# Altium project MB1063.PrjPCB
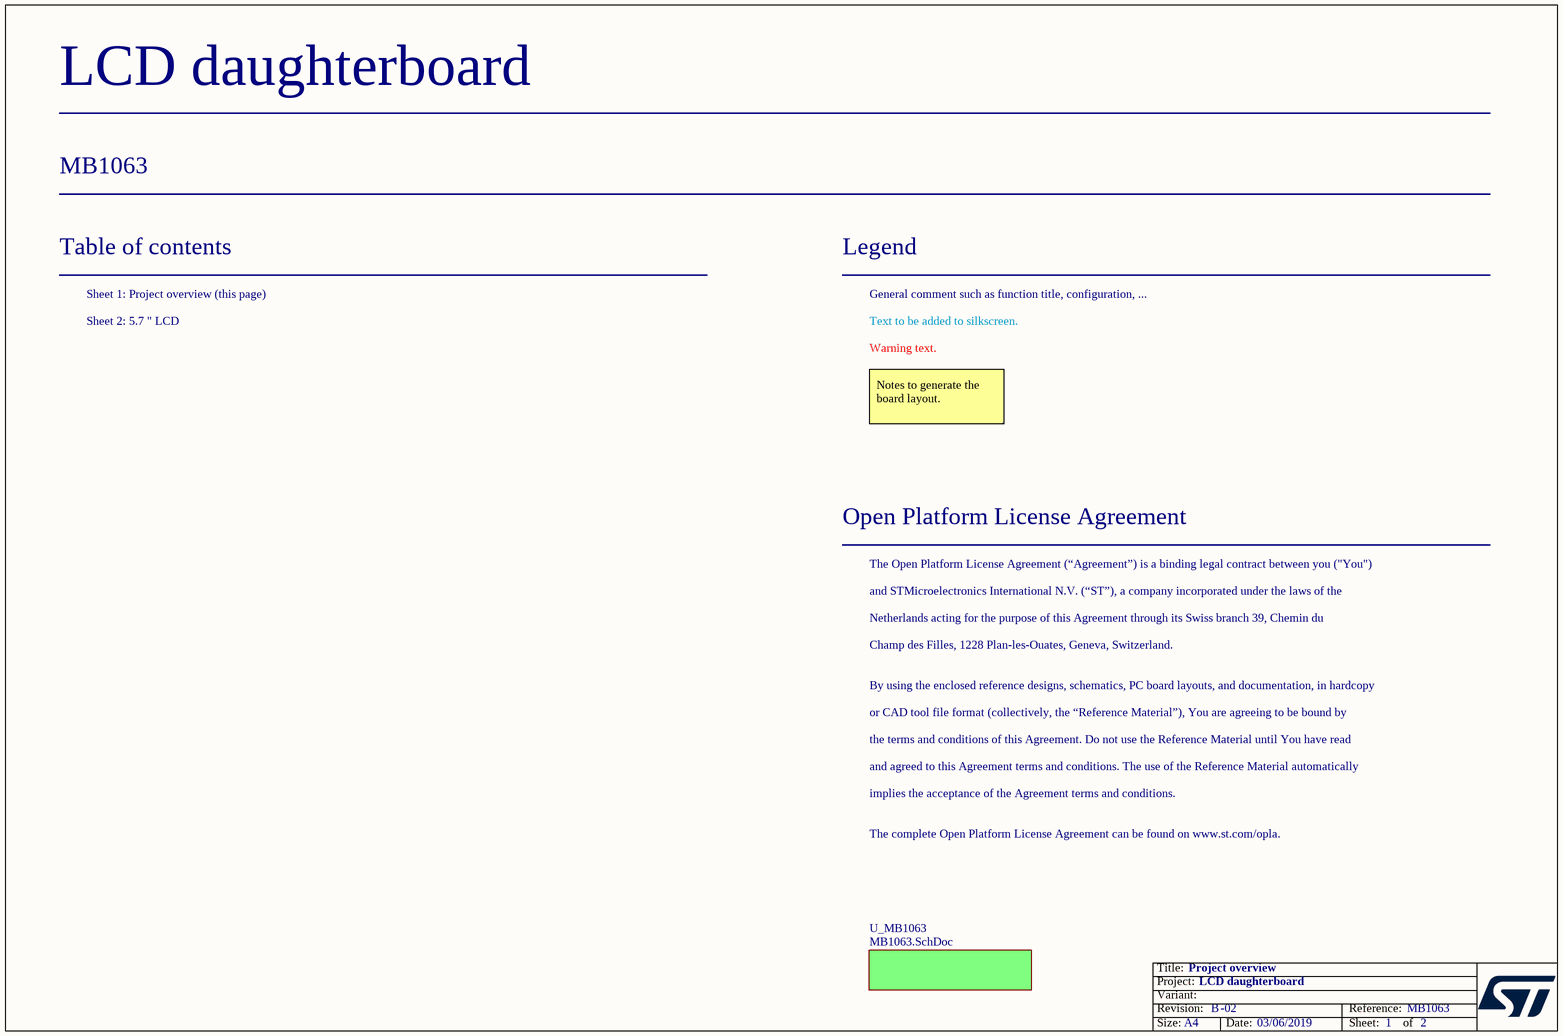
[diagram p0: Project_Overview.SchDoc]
Board_Assembly_Revision: 02; Board_Document_Date: 03/06/2019; Board_Name: LCD daughterboard; Board_PCB_Revision: B; Board_Reference: MB1063
2 sheets, 31 parts. Net scope: global (net labels, ports and power ports of the same name join across sheets).
Sheets:
  Project_Overview.SchDoc
    U_MB1063 = MB1063.SchDoc

## Sheet Project_Overview.SchDoc: Project overview
size A4; Date: Not used; ApprovedBy: Not used; CheckedBy: Not used; Author: Not used; CompanyName: STMicroelectronics; DrawnBy: Not used; Engineer: Not used; Organization: Not used; Address1: Not used; Address2: Not used; Address3: Not used; Address4: Not used; DocumentNumber: 1; Revision: Not used; SheetNumber: 1; SheetTotal: 2

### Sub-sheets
U_MB1063 = MB1063.SchDoc: no entries

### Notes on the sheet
- Table of contents
- Sheet 1: Project overview (this page)
- Legend
- General comment such as function title, configuration, ...
- Sheet 2: 5.7 " LCD
- Text to be added to silkscreen.
- Warning text.
- Notes to generate the board layout.
- Open Platform License Agreement
- The Open Platform License Agreement (“Agreement”) is a binding legal contract between you ("You")
- and STMicroelectronics International N.V. (“ST”), a company incorporated under the laws of the
- Netherlands acting for the purpose of this Agreement through its Swiss branch 39, Chemin du
- Champ des Filles, 1228 Plan-les-Ouates, Geneva, Switzerland.
- By using the enclosed reference designs, schematics, PC board layouts, and documentation, in hardcopy
- or CAD tool file format (collectively, the “Reference Material”), You are agreeing to be bound by
- the terms and conditions of this Agreement. Do not use the Reference Material until You have read
- and agreed to this Agreement terms and conditions. The use of the Reference Material automatically
- implies the acceptance of the Agreement terms and conditions.
- The complete Open Platform License Agreement can be found on www.st.com/opla.

## Sheet MB1063.SchDoc: 5.7 " LCD
size A4; DocumentNumber: 2; Revision: B.2(PCB.SCH); SheetNumber: 2; SheetTotal: 2
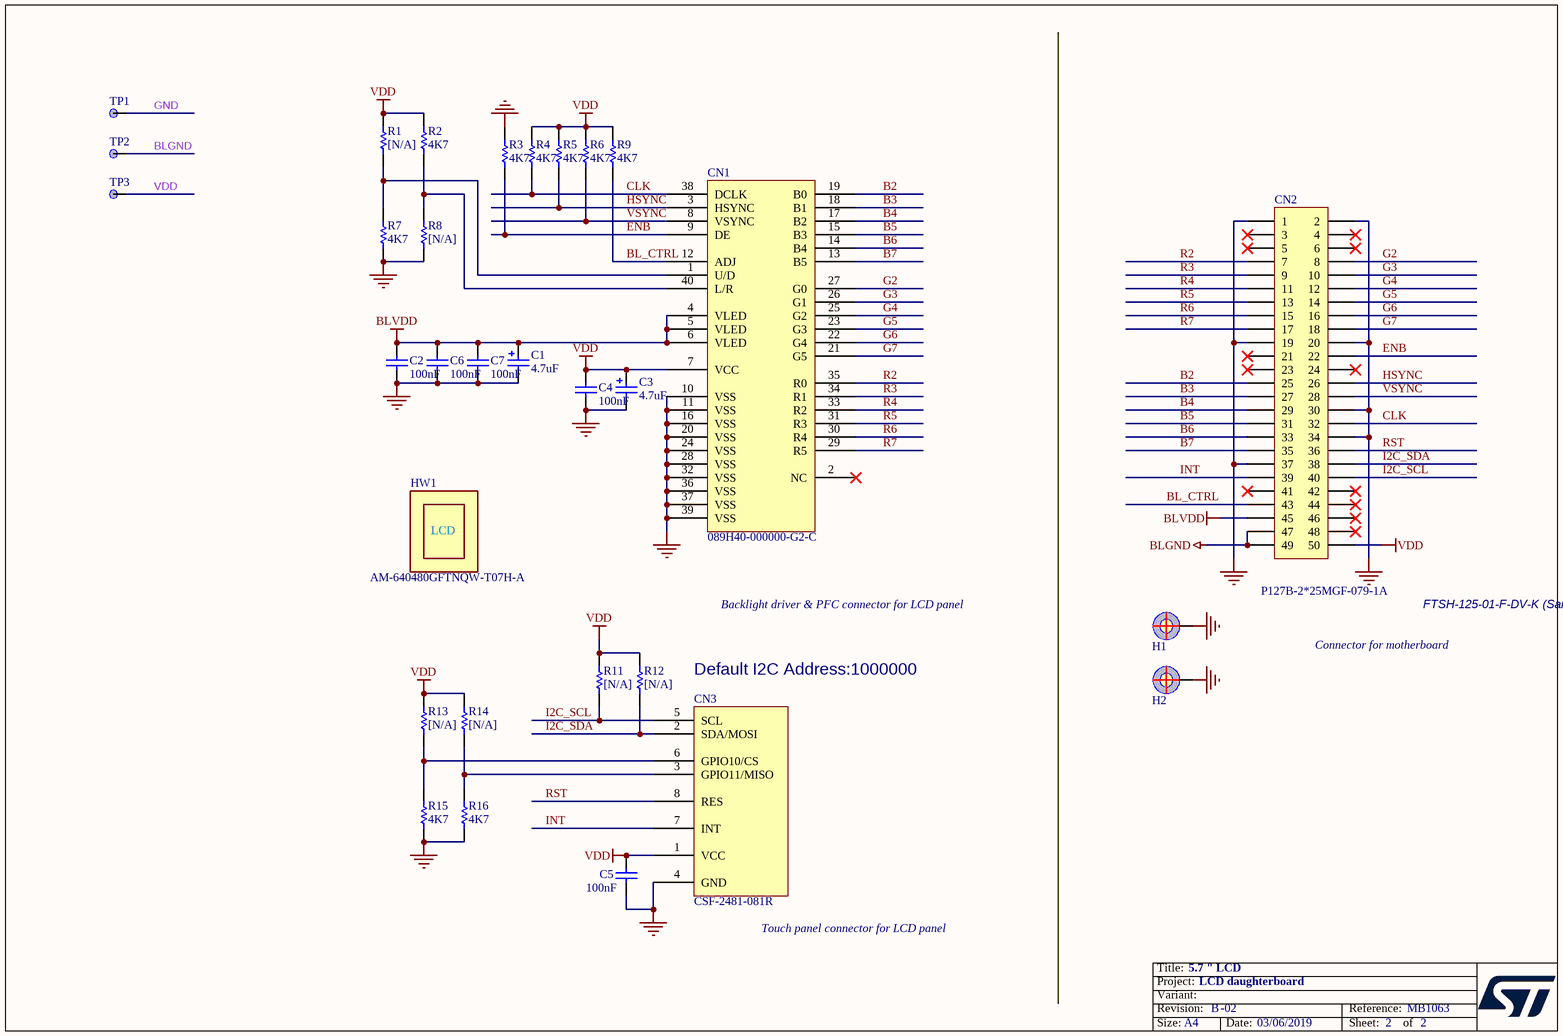
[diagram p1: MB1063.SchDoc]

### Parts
C1  4.7uF  [TAN-A]
C2  100nF  [0603C]
C3  4.7uF  [TAN-A]
C4  100nF  [0603C]
C5  100nF  [0603C]
C6  100nF  [0603C]
C7  100nF  [0603C]
CN1  089H40-000000-G2-C  [FPC40_0R5_089H40LY-FPC_REV]
CN2  P127B-2*25MGF-079-1A  [FTSH-125-01-F-DV]
CN3  CSF-2481-081R  [FPC8_0R5_089H08_LY-FPC_REV]
H1  POSITION HOLE  [HOLE_C9D4R5]  (value not drawn)
H2  POSITION HOLE  [HOLE_C9D4R5]  (value not drawn)
HW1  AM-640480GFTNQW-T07H-A  (mechanical)
R1  [N/A]  [0603R]
R2  4K7  [0603R]
R3  4K7  [0603R]
R4  4K7  [0603R]
R5  4K7  [0603R]
R6  4K7  [0603R]
R7  4K7  [0603R]
R8  [N/A]  [0603R]
R9  4K7  [0603R]
R11  [N/A]  [0603R]
R12  [N/A]  [0603R]
R13  [N/A]  [0603R]
R14  [N/A]  [0603R]
R15  4K7  [0603R]
R16  4K7  [0603R]
TP1  (no value)  [TP]
TP2  (no value)  [TP]
TP3  (no value)  [TP]

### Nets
BLGND: CN2.47 CN2.49 TP2.1
BLVDD: C1.1 C2.2 C6.2 C7.2 CN1.4(VLED) CN1.5(VLED) CN1.6(VLED) CN2.45
GND: C1.2 C2.1 C3.2 C4.1 C5.1 C6.1 C7.1 CN1.10(VSS) CN1.11(VSS) CN1.16(VSS) CN1.20(VSS) CN1.24(VSS) CN1.28(VSS) CN1.32(VSS) CN1.36(VSS) CN1.37(VSS) CN1.39(VSS) CN2.1 CN2.2 CN2.19 CN2.20 CN2.30 CN2.34 CN2.37 CN3.4(GND) H1.1 H2.1 R3.1 R7.2 R8.2 R15.2 R16.2 TP1.1
VDD: C3.1 C4.2 C5.2 CN1.7(VCC) CN2.50 CN3.1(VCC) R1.1 R2.1 R4.1 R5.1 R6.1 R9.1 R11.1 R12.1 R13.1 R14.1 TP3.1
B2: CN1.19(B0) CN2.25
B3: CN1.18(B1) CN2.27
B4: CN1.17(B2) CN2.29
B5: CN1.15(B3) CN2.31
B6: CN1.14(B4) CN2.33
B7: CN1.13(B5) CN2.35
BL_CTRL: CN1.12(ADJ) CN2.43 R9.2
CLK: CN1.38(DCLK) CN2.32 R4.2
ENB: CN1.9(DE) CN2.22 R3.2
G2: CN1.27(G0) CN2.8
G3: CN1.26(G1) CN2.10
G4: CN1.25(G2) CN2.12
G5: CN1.23(G3) CN2.14
G6: CN1.22(G4) CN2.16
G7: CN1.21(G5) CN2.18
HSYNC: CN1.3(HSYNC) CN2.26 R5.2
I2C_SCL: CN2.40 CN3.5(SCL) R11.2
I2C_SDA: CN2.38 CN3.2(SDA/MOSI) R12.2
INT: CN2.39 CN3.7(INT)
R2: CN1.35(R0) CN2.7
R3: CN1.34(R1) CN2.9
R4: CN1.33(R2) CN2.11
R5: CN1.31(R3) CN2.13
R6: CN1.30(R4) CN2.15
R7: CN1.29(R5) CN2.17
RST: CN2.36 CN3.8(RES)
VSYNC: CN1.8(VSYNC) CN2.28 R6.2
NetCN1_1: CN1.1(U/D) R1.2 R7.1
NetCN1_40: CN1.40(L/R) R2.2 R8.1
NetCN3_3: CN3.3(GPIO11/MISO) R14.2 R16.1
NetCN3_6: CN3.6(GPIO10/CS) R13.2 R15.1

Not connected (* = marked no-connect by the designer): CN1 2(NC)*; CN2 3* 4* 5* 6* 21* 23* 24* 41* 42* 44* 46* 48*

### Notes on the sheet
- Backlight driver & PFC connector for LCD panel
- Connector for motherboard
- FTSH-125-01-F-DV-K (Samtec)
- Default I2C Address:1000000
- Touch panel connector for LCD panel

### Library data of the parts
C1 C3 = Cap Pol1: Polarized Capacitor (Radial); Value: 100pF
C2 C4-C7 = CAP: Capacitor; Value: 100pF
CN2 = Header 25X2: Header, 26-Pin, Dual row
HW1 = LCD_MODULE
R1-R9 R11-R16 = Res1: Resistor; Value: 1K
TP1-TP3 = TP

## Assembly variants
Default: not fitted R1 R8 R11 R12 R13 R14 TP1 TP2 TP3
